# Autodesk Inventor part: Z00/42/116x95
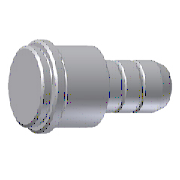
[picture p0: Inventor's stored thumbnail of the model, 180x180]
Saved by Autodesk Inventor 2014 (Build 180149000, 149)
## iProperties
Created: 2009-11
Part Number: Z00/42/116x95
Material: DIN 1.7131
Description: guide pillar
Document SubType Name: Modeling
Designer: gaom
Standard Revision: 1
Manufacturer: HASCO
Language: en-US
Size Designation: 42-116x95
Categories: <MemberInstance><Categories><Category DisplayName="Mold" InternalName="349578f2-f4d4-4954-8c09-8e99297a61c0" Mnemonic="MOLD"><Category DisplayName="Guide Compon
Mass: 4.19143 g
Surface Area: 17.8137 cm^2
Volume: 4.19143 cm^3
Density: 7.85 g/cm^3
Appearance: Steel
IsCustomPart: 0
Author: gaom
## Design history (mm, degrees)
body "Solid1"
revolve "Revolution1" stored, may be unused: angle "d100" = 90 deg
chamfer "Chamfer1" distance "d106" = 0.5; stored, may be unused: second distance "d107" = 2, angle "d108" = 45 deg
fillet "Fillet1" dims "d109" = 0.3
revolve "Revolution2" stored, may be unused: angle "d126" = 90 deg
sketch "Sketch1"
  geometry: L1 (0, -42.393)-(0, 14.066) reference; L2 (0, 22)-(27, 22); L3 (27, 22)-(27, 11); L4 (26.5, 10)-(30, 10); L5 (30, 10)-(30, 0); L6 (30, 0)-(26.5, 0); L7 (27, -1)-(27, -104); L8 (27, -104)-(27, -104); L9 (27, -104)-(27, -106); L10 (27, -106)-(21, -106); L11 (21, -194)-(19.522, -199.518); L12 (17.59, -201)-(0, -201); L13 (21, -106)-(21, -194); L14 (26.5, 0)-(26.5, -1); L15 (26.5, -1)-(27, -1); L16 (26.5, 11)-(27, 11); L17 (26.5, 11)-(26.5, 10); L18 (0, 22)-(0, -201); A1 r 2 centre (17.59, -199) between (17.59, -201) and (19.522, -199.518); 1 further point
  constraints: 38 end point, 7 perpendicular, 6 parallel, 2 collinear, 2 point on circle, 2 point on line, 2 tangent, 2 vertical alignment, 1 centre point, 1 horizontal alignment
  dimensions: "d73" = 10 distance between parallel lines of L6 L4 (derived); "d74" = 12 distance between parallel lines of L2 L4 (derived); "d75" = 116 distance between parallel lines of L10 L4 (derived); "d76" = 2 distance between parallel lines of L10 L8; "d77" = 60 diameter of L5 L1 (derived); "d78" = 95 distance between parallel lines of L12 L10 (derived); "d79" = 54 diameter of L3 L1 (derived); "d89" = 7 distance from line of L12 L11.start (derived); "d92" = 42 diameter of L13 L1 (derived); "d94" = 54 diameter of L7 L1 (derived); "d97" = 2 radius of A1; "d110" = 0.5 distance between parallel lines of L7 L14; "d111" = 1 distance from line of L6.end L15; "d112" = 0.5 distance between parallel lines of L3 L17; "d113" = 1 distance between parallel lines of L4 L16; "d114" = 54 diameter of L9 L18 (derived); "d120" = 15 deg angle of L13 L11
sketch "Sketch2"
  geometry: L1 (-17.59, -201)-(17.59, -201) reference; L2 (0, -40.8)-(0, 6.8) reference; C1 r 2.625 at (21.525, -135.333); C2 r 2.625 at (21.525, -164.667); 1 further point
  constraints: 2 centre point, 1 equal radius, 1 vertical alignment
  dimensions: "d121" = 5.25 diameter of C1 (derived); "d122" = 36.3333 distance from line of L1 C2.centre (derived); "d123" = 65.6667 distance from line of L1 C1.centre (derived); "d129" = 43.05 diameter of C1.centre L2 (derived)
other parameters: "d2" = 54 [user parameter], "l2" = 12 [user parameter], "A_" = 116 [user parameter], "B" = 95 [user parameter], "d1" = 42 [user parameter; used in 1 equation term], "d43" = 42 (= d1), "d91" = 8, "d101" = 0, "d103" = 0, "ob" = 7 [user parameter], "d2_1" = 54 [user parameter], "d2_2" = 54 [user parameter], "B1" = 36.3333 [user parameter], "G1" = 65.6667 [user parameter], "d128" = 0, "L_" = 211 [user parameter]
